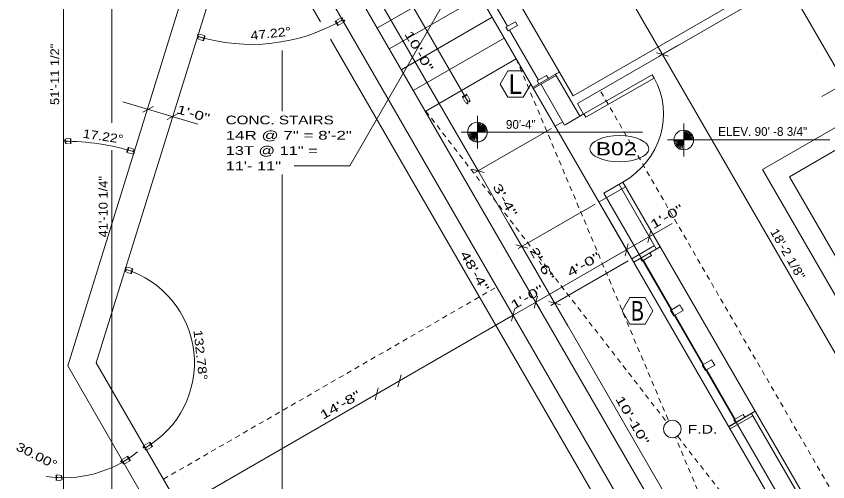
# Model space of a CAD drawing. Extents: x 7 to 126, y 6 to 93.
# Drawn here: x 6.57 to 37.51, y 44.6 to 62.37 of the extents above; entities that cross this region are included whole.
import ezdxf
from ezdxf.enums import TextEntityAlignment as Align

# ---------------------------------------------------------------- set-up
doc = ezdxf.new("R2010")
doc.units = 0
doc.header["$LTSCALE"] = 0.13
doc.linetypes.add('SHORT_DASHED', pattern=[2.7, 1.5, -1.2])
for name, color, linetype, lineweight in [('13', 7, 'Continuous', 13), ('14', 7, 'Continuous', 13), ('15', 7, 'Continuous', 13), ('16', 7, 'Continuous', 13), ('17', 7, 'Continuous', 13), ('22', 7, 'SHORT_DASHED', 13), ('24', 7, 'Continuous', 13), ('34', 7, 'Continuous', 13), ('4', 7, 'Continuous', 13), ('40', 7, 'Continuous', 13), ('42', 7, 'Continuous', 13), ('50', 7, 'Continuous', 13), ('53', 7, 'Continuous', 13), ('6', 7, 'SHORT_DASHED', 13), ('7', 7, 'Continuous', 13)]:
    doc.layers.add(name, color=color, linetype=linetype, lineweight=lineweight)

msp = doc.modelspace()

# ---------------------------------------------------------------- linework, layer by layer
at = {"layer": '13'}
for p, q in [((27.4789, 58.2159), (26.5831, 59.7676)), ((28.2124, 58.6421), (27.4977, 58.2294)), ((29.7036, 56.0389), (28.9778, 55.6199)), ((28.9778, 55.6199), (35.7268, 43.9303))]:
    msp.add_line(p, q, dxfattribs=at)
at = {"layer": '14'}
msp.add_lwpolyline([(115.8724, 34.3511), (77.539, 34.3511), (75.8724, 37.2379), (59.2057, 37.2379), (57.539, 34.3511), (40.8724, 34.3511), (16.7057, 76.209), (22.539, 86.3127), (34.2057, 86.3127), (44.2057, 68.9922), (60.8724, 68.9922)], dxfattribs=at)
at = {"layer": '15'}
for p, q in [((26.289, 59.6102), (27.155, 60.1102)), ((28.0563, 58.5493), (27.124, 60.1641)), ((27.1223, 58.1668), (27.411, 58.3335)), ((28.789, 55.2801), (29.7994, 55.8634)), ((30.9729, 53.4975), (29.5551, 55.9532)), ((30.039, 53.115), (30.905, 53.615)), ((33.789, 46.6198), (34.655, 47.1198)), ((36.3842, 44.1248), (34.6032, 47.2098))]:
    msp.add_line(p, q, dxfattribs=at)
at = {"layer": '16'}
for p, q in [((23.9221, 64.3641), (25.297, 61.9829)), ((25.2428, 61.9516), (25.6037, 62.1599)), ((25.3262, 61.8073), (25.2428, 61.9516)), ((25.687, 62.0156), (25.3262, 61.8073)), ((25.687, 62.0156), (25.6037, 62.1599)), ((26.4836, 59.9275), (25.3803, 61.8385)), ((26.2755, 59.663), (27.2731, 60.239)), ((26.4295, 59.8963), (26.7904, 60.1046)), ((26.7904, 60.1046), (26.8506, 60.0003)), ((26.4295, 59.8963), (26.4897, 59.792)), ((30.1129, 52.9889), (31.1232, 53.5722)), ((30.149, 53.0097), (31.015, 53.5097)), ((30.428, 53.0265), (30.7888, 53.2348)), ((30.7888, 53.2348), (30.7286, 53.3391)), ((30.428, 53.0265), (30.3678, 53.1308)), ((30.4821, 53.0577), (31.5701, 51.1731)), ((31.516, 51.1419), (31.8769, 51.3502)), ((31.516, 51.1419), (31.5762, 51.0376)), ((31.6364, 50.9333), (31.9973, 51.1416)), ((31.8769, 51.3502), (31.9371, 51.2459)), ((31.9973, 51.1416), (31.9371, 51.2459)), ((31.6364, 50.9333), (31.5762, 51.0376)), ((31.6906, 50.9645), (32.776, 49.0844)), ((32.7219, 49.0532), (33.0828, 49.2615)), ((33.0828, 49.2615), (33.143, 49.1572)), ((32.7219, 49.0532), (32.7821, 48.9489)), ((32.8423, 48.8446), (32.7821, 48.9489)), ((32.8423, 48.8446), (33.2032, 49.0529)), ((33.2032, 49.0529), (33.143, 49.1572)), ((32.8965, 48.8759), (33.9821, 46.9955)), ((33.7379, 46.7102), (34.7482, 47.2935)), ((33.7739, 46.731), (34.64, 47.231)), ((33.9279, 46.9643), (34.2888, 47.1726)), ((34.2888, 47.1726), (34.349, 47.0683)), ((33.9279, 46.9643), (33.9882, 46.86))]:
    msp.add_line(p, q, dxfattribs=at)
at = {"layer": '17'}
msp.add_lwpolyline([(28.2124, 58.6421), (28.2849, 58.5155), (30.8881, 60.0067), (30.8156, 60.1332)], close=True, dxfattribs=at)
msp.add_ellipse((28.2849, 58.5155), major_axis=(2.6032, 1.4911), ratio=0.951389, start_param=4.712389, end_param=6.2831853, dxfattribs=at)
at = {"layer": '22'}
msp.add_line((12.1859, 44.7043), (24.8876, 52.0376), dxfattribs=at)
msp.add_lwpolyline([(55.7108, 36.5178), (42.1233, 36.5178), (28.8321, 59.5389)], dxfattribs=at)
at = {"layer": '24'}
for p, q in [((27.7994, 59.3275), (20.9661, 71.1632)), ((28.2006, 58.6326), (27.9661, 59.0389))]:
    msp.add_line(p, q, dxfattribs=at)
msp.add_lwpolyline([(56.2881, 35.5178), (41.5459, 35.5178), (29.6995, 56.0365)], dxfattribs=at)
at = {"layer": '34'}
for points in [[(39.5727, 59.145), (35.0261, 56.5199), (39.9011, 48.0762), (44.4477, 50.7012)], [(39.2982, 58.1204), (36.0506, 56.2454), (40.1756, 49.1007), (43.4232, 50.9757)]]:
    msp.add_lwpolyline(points, close=True, dxfattribs=at)
at = {"layer": '4'}
for p, q in [((15.2674, 70.7296), (8.5387, 49.0213)), ((37.9856, 31.3511), (15.2614, 70.7105)), ((15.9427, 69.5306), (9.6233, 49.1428)), ((37.4082, 30.3511), (15.5393, 68.2293)), ((20.3507, 61.925), (23.8031, 63.9183)), ((20.809, 61.1312), (24.2615, 63.1244)), ((21.2674, 60.3373), (24.7198, 62.3306)), ((21.7257, 59.5435), (25.1781, 61.5367)), ((22.184, 58.7496), (25.6365, 60.7429)), ((22.7821, 24.3511), (8.5387, 49.0213)), ((23.3594, 25.3511), (9.6233, 49.1428))]:
    msp.add_line(p, q, dxfattribs=at)
at = {"layer": '40'}
for p, q in [((24.1562, 58.3227), (24.1562, 58.5727)), ((24.1562, 57.9479), (24.2042, 58.3195)), ((24.1562, 57.9479), (24.2616, 58.3074)), ((24.1562, 57.9479), (24.3031, 58.2927)), ((24.1562, 57.9479), (24.3541, 58.266)), ((24.1562, 57.9479), (24.4026, 58.2303)), ((24.1562, 57.9479), (24.4368, 58.1965)), ((32.0208, 58.0206), (32.0208, 58.2706)), ((23.7815, 57.9479), (23.5315, 57.9479)), ((24.1562, 57.9479), (23.7828, 57.918)), ((24.1562, 57.9479), (23.7892, 57.8714)), ((24.1562, 57.9479), (23.8009, 57.8286)), ((24.1562, 57.9479), (23.8175, 57.788)), ((24.1562, 57.9479), (23.8437, 57.7417)), ((24.1562, 57.9479), (23.8756, 57.6994)), ((24.1562, 57.9479), (23.9147, 57.6616)), ((24.1562, 57.9479), (23.9678, 57.6238)), ((24.1562, 57.9479), (24.0182, 57.6052)), ((24.1562, 57.9479), (24.0882, 57.5796)), ((24.1562, 57.9479), (24.4631, 58.163)), ((24.1562, 57.9479), (24.4859, 58.1259)), ((24.1562, 57.9479), (24.5016, 58.0932)), ((24.1562, 57.9479), (24.5145, 58.0579)), ((24.1562, 57.9479), (24.5229, 58.0266)), ((24.1562, 57.9479), (24.5287, 57.9899)), ((24.1562, 57.9479), (24.531, 57.9479)), ((24.1562, 57.5732), (24.1562, 57.9479)), ((30.4479, 57.9479), (24.531, 57.9479)), ((32.0208, 57.6458), (32.0688, 58.0174)), ((32.0208, 57.6458), (32.1262, 58.0053)), ((32.0208, 57.6458), (32.1677, 57.9906)), ((32.0208, 57.6458), (32.2187, 57.9639)), ((32.0208, 57.6458), (32.2672, 57.9282)), ((32.0208, 57.6458), (32.3014, 57.8945)), ((32.0208, 57.6458), (32.3277, 57.8609)), ((24.1562, 57.3232), (24.1562, 57.5732)), ((31.6461, 57.6458), (31.3961, 57.6458)), ((32.0208, 57.6458), (31.6474, 57.6159)), ((32.0208, 57.6458), (31.6538, 57.5694)), ((32.0208, 57.6458), (31.6655, 57.5265)), ((32.0208, 57.6458), (31.6821, 57.4859)), ((32.0208, 57.6458), (31.7082, 57.4396)), ((32.0208, 57.6458), (31.7402, 57.3974)), ((32.0208, 57.6458), (31.7793, 57.3596)), ((32.0208, 57.6458), (31.8324, 57.3217)), ((32.0208, 57.6458), (31.8828, 57.3031)), ((32.0208, 57.6458), (31.9528, 57.2775)), ((32.0208, 57.6458), (32.3504, 57.8238)), ((32.0208, 57.6458), (32.3662, 57.7911)), ((32.0208, 57.6458), (32.3791, 57.7558)), ((32.0208, 57.6458), (32.3875, 57.7245)), ((32.0208, 57.6458), (32.3933, 57.6878)), ((32.0208, 57.6458), (32.3956, 57.6458)), ((32.0208, 57.2711), (32.0208, 57.6458)), ((32.6456, 57.6458), (32.3956, 57.6458)), ((32.3958, 57.6458), (37.5833, 57.6458)), ((32.0208, 57.0211), (32.0208, 57.2711))]:
    msp.add_line(p, q, dxfattribs=at)
for points in [[(23.7815, 57.9479), (24.1562, 57.9479), (24.1562, 58.3227)], [(31.6461, 57.6458), (32.0208, 57.6458), (32.0208, 58.0206)]]:
    msp.add_lwpolyline(points, dxfattribs=at)
for centre in [(24.1562, 57.9479), (32.0208, 57.6458)]:
    msp.add_circle(centre, 0.375, dxfattribs=at)
at = {"layer": '42'}
for points in [[(26.1875, 59.7812), (25.8958, 60.2864), (25.3125, 60.2864), (25.0208, 59.7812), (25.3125, 59.2761), (25.8958, 59.2761)], [(30.839, 51.1261), (30.5474, 51.6313), (29.964, 51.6313), (29.6724, 51.1261), (29.964, 50.621), (30.5474, 50.621)]]:
    msp.add_lwpolyline(points, close=True, dxfattribs=at)
msp.add_ellipse((29.5625, 57.3125), major_axis=(1.1204, 0), ratio=0.446291, dxfattribs=at)
at = {"layer": '50'}
for p, q in [((8.375, 86.3127), (8.375, 34.3511)), ((10.2188, 76.209), (10.2188, 58.3021)), ((11.7211, 73.3312), (18.1721, 62.1578)), ((24.0386, 73.3221), (31.2053, 60.909)), ((19.1822, 65.1296), (24.1822, 56.4693)), ((36.0231, 63.4981), (38.2368, 59.6639)), ((37.2874, 59.3082), (41.4732, 61.7249)), ((35.8878, 31.4733), (18.5561, 61.4926)), ((16.7057, 61.0625), (16.7057, 58.7396)), ((31.433, 60.848), (30.9777, 60.97)), ((30.9777, 60.97), (31.433, 60.848)), ((30.9777, 60.97), (31.433, 60.848)), ((31.8086, 61.2573), (31.061, 60.8257)), ((31.8086, 61.2573), (31.061, 60.8257)), ((31.2053, 60.909), (40.2936, 45.1677)), ((10.6413, 59.1022), (13.4959, 58.2532)), ((11.8071, 58.9294), (11.3926, 58.7049)), ((12.3301, 58.4261), (12.7446, 58.6505)), ((12.3301, 58.426), (12.7446, 58.6505)), ((12.5338, 58.5263), (12.4899, 58.3785)), ((26.978, 58.0835), (24.0378, 56.386)), ((10.2188, 34.3511), (10.2188, 57.2579)), ((23.6822, 57.3353), (26.3489, 52.7166)), ((16.7057, 14.5521), (16.7057, 56.3333)), ((24.4098, 56.4083), (23.9545, 56.5303)), ((24.4098, 56.4083), (23.9545, 56.5303)), ((28.6447, 55.1967), (25.7045, 53.4992)), ((28.8724, 55.1358), (29.9246, 53.3133)), ((28.9752, 52.9577), (31.5733, 54.4577)), ((30.3474, 54.581), (30.7906, 53.8133)), ((25.3489, 54.4486), (27.5989, 50.5515)), ((30.6462, 53.73), (30.7682, 54.1853)), ((25.6212, 53.6436), (26.0765, 53.5216)), ((26.0765, 53.5216), (25.6212, 53.6436)), ((29.9022, 53.6853), (29.7802, 53.23)), ((29.9022, 53.6853), (29.7802, 53.23)), ((29.8412, 53.4577), (26.3771, 51.4576)), ((29.8947, 53.0317), (26.9545, 51.3342)), ((24.6451, 50.4576), (27.2431, 51.9576)), ((24.9709, 51.8933), (25.5944, 50.8133)), ((26.3161, 51.23), (26.4381, 51.6853)), ((26.3161, 51.23), (26.4381, 51.6853)), ((26.5402, 51.1751), (26.2938, 51.602)), ((26.8712, 51.4785), (27.3265, 51.3565)), ((26.8712, 51.4785), (27.3265, 51.3565)), ((27.0989, 51.4175), (32.5155, 42.0356)), ((29.0018, 44.9116), (25.4277, 51.102)), ((25.5721, 51.1853), (25.4501, 50.73)), ((25.5721, 51.1853), (25.4501, 50.73)), ((25.5721, 51.1853), (25.4501, 50.73)), ((12.8094, 43.6243), (25.5111, 50.9576)), ((21.1207, 48.2304), (21.2427, 48.6857)), ((20.3759, 48.1853), (20.2539, 47.73))]:
    msp.add_line(p, q, dxfattribs=at)
for points in [[(23.7917, 59.1146), (16.2078, 72.2502), (14.9271, 72.2502)], [(22.7708, 62.6979), (19.2859, 56.6618), (17.1667, 56.6618)]]:
    msp.add_lwpolyline(points, dxfattribs=at)
for centre, radius, start, end in [((15.5393, 68.2293), 6.9353, 252.77884, 299.99996), ((8.375, 48.4931), 9.1044, 72.77879, 90), ((9.6233, 49.1428), 3.7418, 300.0002, 72.77879), ((8.375, 49.3049), 4.5473, 261.60009, 308.39988)]:
    msp.add_arc(centre, radius, start, end, dxfattribs=at)
at = {"layer": '53'}
for p, q in [((27.7994, 59.3275), (35.6958, 63.8865)), ((27.9661, 59.0389), (35.9398, 63.6425))]:
    msp.add_line(p, q, dxfattribs=at)
at = {"layer": '6'}
for p, q in [((25.6365, 60.7429), (31.4566, 46.8907)), ((22.184, 58.7496), (31.3849, 46.8625)), ((37.9856, 31.3511), (31.6949, 46.3234)), ((40.295, 35.3511), (31.7616, 46.3759))]:
    msp.add_line(p, q, dxfattribs=at)
at = {"layer": '6', "linetype": 'Continuous'}
msp.add_circle((31.5834, 46.6185), 0.3333, dxfattribs=at)
at = {"layer": '7'}
msp.add_lwpolyline([(115.8724, 34.3511), (77.539, 34.3511), (75.8724, 37.2379), (59.2057, 37.2379), (57.539, 34.3511), (40.8724, 34.3511), (16.7057, 76.209), (22.539, 86.3127), (34.2057, 86.3127), (44.2057, 68.9922), (60.8724, 68.9922), (64.2057, 63.2187), (65.039, 63.2187), (75.039, 63.2187), (80.039, 71.8789), (96.7057, 71.8789), (98.789, 75.4873), (113.4884, 75.4873), (121.0473, 51.0685)], dxfattribs=at)

# ---------------------------------------------------------------- texts
at = {"layer": '40'}
for s, p in [('90\'-4"      ', (25.2396, 58.0729)), ('ELEV. 90\' -8 3/4"', (33.3333, 57.8021))]:
    msp.add_text(s, height=0.3333, dxfattribs=at).set_placement(p)
at = {"layer": '42'}
for s, height, width, p in [('L', 0.75, 0.9, (25.6042, 59.4062)), ('B02 ', 0.5, 1.3, (29.5625, 57.0625)), ('B', 0.75, 0.75, (30.2557, 50.7511))]:
    msp.add_text(s, height=height, dxfattribs=dict(at, width=width)).set_placement(p, align=Align.CENTER)
at = {"layer": '50'}
for rotation, width, p in [(30, 2.35, (19.1736, 62.191)), (162.779, 2.05, (13.4531, 61.7314)), (300, 2.35, (23.7596, 58.9479)), (180, 1.7, (8.375, 57.7085)), (342.779, 2.05, (11.1033, 57.0627)), (162.779, 2.05, (10.6982, 52.8433)), (210, 2.35, (11.3275, 45.9344)), (210, 2.35, (10.482, 45.3989))]:
    msp.add_text('B', height=0.2222, rotation=rotation, dxfattribs=dict(at, width=width)).set_placement(p, align=Align.RIGHT)
for s, rotation, width, p in [('47.22°', 6.389, 1.2, (15.5234, 61.4596)), ('10\'-0"', 300, 1.5, (21.358, 61.6942)), ('51\'-11 1/2"', 90, 1.1, (8.2083, 58.9802)), ('1\'-0"', 343.436, 1.45, (12.6588, 58.676)), ('17.22°', 351.389, 1.2, (9.0912, 57.7359)), ('41\'-10 1/4"', 90, 1.1, (10.0521, 53.9284)), ('3\'-4"', 300, 1.55, (24.722, 55.8677)), ('1\'-0"', 30, 1.55, (30.8592, 54.2378)), ('18\'-2 1/8"', 300, 1.15, (35.3006, 54.1491)), ('2\'-6"', 300, 1.55, (26.129, 53.4307)), ('48\'-4"', 300, 1.5, (23.4803, 53.297)), ('4\'-0"', 30, 1.55, (27.6913, 52.4089)), ('1\'-0"', 30, 1.55, (25.536, 51.1645)), ('132.78°', 276.389, 1.25, (13.3261, 50.3817)), ('14\'-8"', 30, 1.5, (18.2654, 46.9668)), ('10\'-10"', 300, 1.5, (29.4004, 47.7645)), ('30.00°', 332.943, 1.3, (6.5276, 45.8368))]:
    msp.add_text(s, height=0.3333, rotation=rotation, dxfattribs=dict(at, width=width)).set_placement(p)
for s, width, p in [('CONC. STAIRS ', 1.3, (14.5566, 58.2425)), ('14R @ 7" = 8\'-2"  ', 1.45, (14.5566, 57.6591)), ('13T @ 11" =  ', 1.4, (14.5566, 57.0758)), ('11\'- 11"', 1.4, (14.5566, 56.4925))]:
    msp.add_text(s, height=0.3333, dxfattribs=dict(at, width=width)).set_placement(p)
at = {"layer": '50', "width": 1.7}
msp.add_text('B', height=0.2222, dxfattribs=at).set_placement((8.375, 44.6465), align=Align.RIGHT)
at = {"layer": '6', "width": 1.35}
msp.add_text('F.D.', height=0.3333, dxfattribs=at).set_placement((32.1667, 46.4414))

doc.saveas('drawing.dxf')
